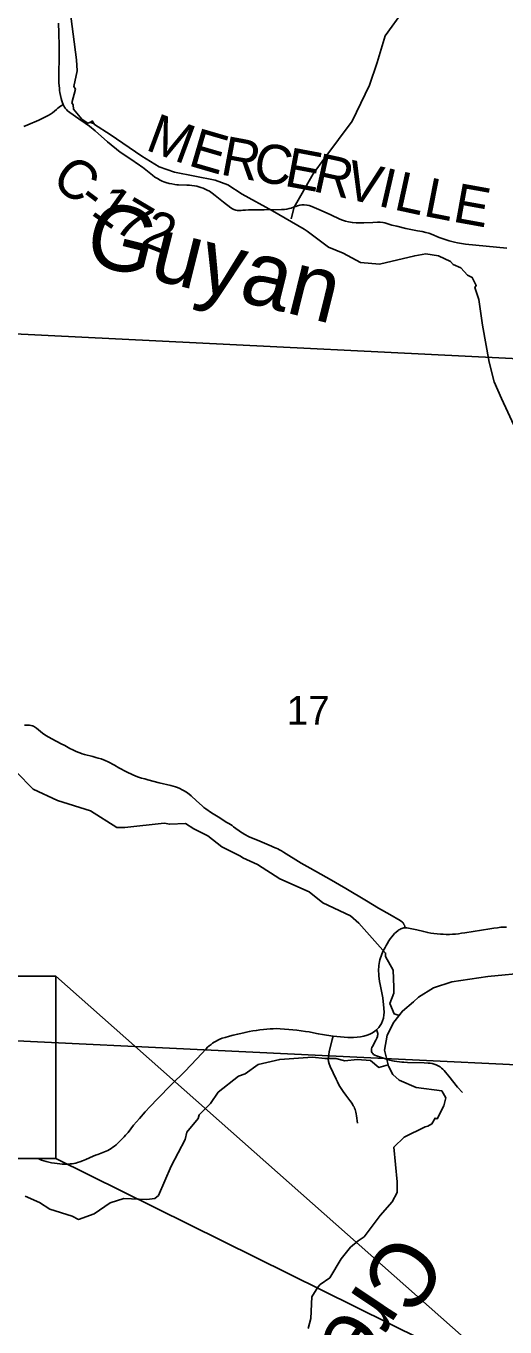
# Model space of a CAD drawing. Extents: x -2.1 to 31.9, y 6.3 to 28.3.
# Drawn here: x 2.564 to 3.259, y 23.525 to 25.414 of the extents above; entities that cross this region are included whole.
import ezdxf

# ---------------------------------------------------------------- set-up
doc = ezdxf.new("R2010")
doc.units = 0
for name, color, linetype in [('GM_X_County_Road', 7, 'Continuous'), ('GM_X_County_Road_Text', 7, 'Continuous'), ('GM_X_Minor_River', 7, 'Continuous'), ('GM_X_Minor_River_Text', 7, 'Continuous'), ('GM_X_Section', 7, 'Continuous'), ('GM_X_Section_Text', 7, 'Continuous'), ('GM_X_Township_Road', 7, 'Continuous'), ('TX_P_1', 7, 'Continuous')]:
    doc.layers.add(name, color=color, linetype=linetype)

msp = doc.modelspace()

# ---------------------------------------------------------------- linework, layer by layer
at = {"layer": 'GM_X_County_Road'}
for points in [[(2.611, 25.4185), (2.6113, 25.4136), (2.6115, 25.409), (2.6118, 25.403), (2.6119, 25.3974), (2.612, 25.3916), (2.612, 25.3708), (2.6117, 25.343), (2.6117, 25.3376), (2.6119, 25.3318), (2.6122, 25.3276), (2.6125, 25.3238), (2.6129, 25.3206), (2.6133, 25.3176), (2.6141, 25.3132), (2.615, 25.3091), (2.6159, 25.3056), (2.6168, 25.3027), (2.6179, 25.3001), (2.6188, 25.2983), (2.6198, 25.2966), (2.621, 25.2949), (2.6227, 25.293), (2.6245, 25.2912), (2.6276, 25.2887), (2.6405, 25.2795), (2.6454, 25.2763), (2.6498, 25.2733), (2.656, 25.2687), (2.6643, 25.2619), (2.6825, 25.2461), (2.7007, 25.2311), (2.7177, 25.2198), (2.7258, 25.2143), (2.7285, 25.2127), (2.7309, 25.211), (2.7331, 25.2093), (2.7477, 25.1975), (2.751, 25.195), (2.7547, 25.1927), (2.7587, 25.1906), (2.7614, 25.1892), (2.7641, 25.1881), (2.7668, 25.1872), (2.7717, 25.1858), (2.7759, 25.1849), (2.7798, 25.1843), (2.7828, 25.1839), (2.7855, 25.1837), (2.7973, 25.1834), (2.8013, 25.1832), (2.8048, 25.1828), (2.8084, 25.1822), (2.812, 25.1815), (2.815, 25.1807), (2.8178, 25.1798), (2.8212, 25.1786), (2.8242, 25.1774), (2.8271, 25.1761), (2.8301, 25.1743), (2.8342, 25.1717), (2.8385, 25.1682), (2.8505, 25.1586), (2.8612, 25.1501), (2.8636, 25.1487), (2.8658, 25.1477), (2.8683, 25.1468), (2.8708, 25.1463), (2.8736, 25.1462), (2.8762, 25.1464), (2.8789, 25.1467), (2.8826, 25.147), (2.8871, 25.1472), (2.9098, 25.1474), (2.9348, 25.1479), (2.9391, 25.1481), (2.9427, 25.1485), (2.9461, 25.1492), (2.949, 25.15), (2.9533, 25.1515), (2.9554, 25.1523), (2.9582, 25.1533), (2.9616, 25.1542), (2.9645, 25.1546), (2.9678, 25.1546), (2.9716, 25.1542), (2.975, 25.1535), (2.9789, 25.1521), (2.9922, 25.1463), (3.0062, 25.1399), (3.0192, 25.134), (3.0231, 25.1325), (3.0275, 25.131), (3.0321, 25.1299), (3.0377, 25.1289), (3.0432, 25.1284), (3.0483, 25.1283), (3.0542, 25.1284), (3.0675, 25.1289), (3.074, 25.1294), (3.0781, 25.1296), (3.0818, 25.1292), (3.0849, 25.1285), (3.0949, 25.1253), (3.102, 25.1236), (3.1153, 25.1204), (3.1323, 25.1171), (3.139, 25.1159), (3.1444, 25.1146), (3.1485, 25.1134), (3.1525, 25.1119), (3.1637, 25.1074), (3.1737, 25.1038), (3.1778, 25.1025), (3.182, 25.1013), (3.186, 25.1003), (3.19, 25.0996), (3.2016, 25.0977), (3.2318, 25.0944), (3.2618, 25.0916)], [(2.5618, 24.3989), (2.5645, 24.3992), (2.5667, 24.3992), (2.5692, 24.3991), (2.5713, 24.3987), (2.5734, 24.3982), (2.575, 24.3975), (2.5765, 24.3966), (2.5792, 24.3947), (2.5882, 24.3877), (2.593, 24.3843), (2.6018, 24.3795), (2.6153, 24.3722), (2.6202, 24.3695), (2.6278, 24.3654), (2.6319, 24.3634), (2.6361, 24.3615), (2.6391, 24.3601), (2.6421, 24.359), (2.6455, 24.3577), (2.6491, 24.3567), (2.6611, 24.3535), (2.6652, 24.3524), (2.669, 24.3514), (2.673, 24.3502), (2.6787, 24.3479), (2.6832, 24.3458), (2.6925, 24.3408), (2.6989, 24.3371), (2.7099, 24.3314), (2.7193, 24.327), (2.726, 24.3242), (2.7316, 24.3224), (2.7363, 24.321), (2.7408, 24.3197), (2.7575, 24.3156), (2.7744, 24.3114), (2.7776, 24.3105), (2.7809, 24.3096), (2.7841, 24.3085), (2.7872, 24.3071), (2.7908, 24.3054), (2.7937, 24.3037), (2.7961, 24.3022), (2.7984, 24.3007), (2.8036, 24.2964), (2.8114, 24.2893), (2.8197, 24.2819), (2.8223, 24.2797), (2.825, 24.2776), (2.8333, 24.2717), (2.8429, 24.2658), (2.8557, 24.258), (2.8583, 24.2564), (2.8607, 24.2549), (2.863, 24.2534), (2.8653, 24.2517), (2.8768, 24.2433), (2.8787, 24.2421), (2.8805, 24.241), (2.888, 24.2372), (2.9034, 24.2305), (2.9203, 24.2236), (2.9234, 24.2222), (2.9269, 24.2207), (2.9294, 24.2194), (2.932, 24.2181), (2.9346, 24.2165), (2.9378, 24.2145), (2.9634, 24.1988), (2.9765, 24.1914), (3.0074, 24.174), (3.0189, 24.1674), (3.028, 24.1618), (3.0579, 24.144), (3.0753, 24.1336), (3.0918, 24.1243), (3.107, 24.1153), (3.109, 24.114), (3.1102, 24.1131), (3.1109, 24.1124), (3.1114, 24.1117), (3.1121, 24.1106), (3.1125, 24.1096), (3.113, 24.1085), (3.114, 24.105)], [(2.5817, 23.7698), (2.5835, 23.769), (2.5868, 23.7676), (2.5901, 23.7665), (2.5934, 23.7655), (2.5973, 23.7646), (2.6013, 23.7637), (2.6052, 23.7631), (2.6091, 23.7625), (2.613, 23.7621), (2.6165, 23.7619), (2.6196, 23.7618), (2.6227, 23.7617), (2.6256, 23.7618), (2.6282, 23.762), (2.631, 23.7622), (2.6335, 23.7626), (2.6362, 23.7632), (2.639, 23.764), (2.6422, 23.765), (2.6459, 23.7666), (2.6507, 23.7687), (2.6615, 23.7733), (2.6647, 23.7746), (2.6681, 23.7758), (2.6755, 23.7785), (2.6781, 23.7795), (2.6804, 23.7806), (2.6827, 23.7817), (2.6852, 23.7831), (2.6876, 23.7846), (2.69, 23.7863), (2.6923, 23.7879), (2.6947, 23.7898), (2.6966, 23.7915), (2.6988, 23.7935), (2.7017, 23.7963), (2.7043, 23.799), (2.7065, 23.8013), (2.7086, 23.8038), (2.7121, 23.8078), (2.7202, 23.8181), (2.7245, 23.8233), (2.7286, 23.828), (2.7372, 23.8378), (2.7444, 23.8455), (2.755, 23.8566), (2.7753, 23.8772), (2.7943, 23.8962), (2.8121, 23.9148), (2.8254, 23.9292), (2.8276, 23.9314), (2.8299, 23.9335), (2.8326, 23.9356), (2.8347, 23.9373), (2.8371, 23.9389), (2.8398, 23.9404), (2.8426, 23.9418), (2.8455, 23.9431), (2.8487, 23.9444), (2.853, 23.9458), (2.8591, 23.9475), (2.8646, 23.949), (2.8713, 23.9506), (2.882, 23.9529), (2.8881, 23.9541), (2.8931, 23.9551), (2.8983, 23.956), (2.9033, 23.9567), (2.9088, 23.9573), (2.9133, 23.9577), (2.9184, 23.9581), (2.9226, 23.9583), (2.9271, 23.9585), (2.9327, 23.9583), (2.939, 23.9579), (2.9454, 23.9574), (2.9513, 23.9569), (2.9572, 23.9563), (2.9634, 23.9555), (2.9695, 23.9545), (2.975, 23.9536), (2.9814, 23.9523), (2.988, 23.9511), (2.9943, 23.9499), (3.0002, 23.9489), (3.0096, 23.9476), (3.0311, 23.9457), (3.035, 23.9455), (3.0391, 23.9455), (3.0444, 23.9459), (3.0496, 23.9466), (3.0543, 23.9475), (3.0589, 23.9489), (3.0629, 23.9504), (3.067, 23.9525), (3.0703, 23.9548), (3.0727, 23.9568), (3.076, 23.9602), (3.0778, 23.9628), (3.0798, 23.9661), (3.0813, 23.9696), (3.0826, 23.9739), (3.0834, 23.9783), (3.0836, 23.982), (3.0834, 23.9882), (3.0829, 23.9937), (3.0823, 23.9979), (3.0816, 24.003), (3.0778, 24.0228), (3.0771, 24.0269), (3.0764, 24.0314), (3.076, 24.0349), (3.0758, 24.0384), (3.0757, 24.0415), (3.0757, 24.0447), (3.0759, 24.0476), (3.0761, 24.0502), (3.0765, 24.0531), (3.0769, 24.0559), (3.0776, 24.0585), (3.0784, 24.0611), (3.0792, 24.0636), (3.0804, 24.0667), (3.0813, 24.069), (3.0823, 24.0714), (3.0837, 24.074), (3.085, 24.0765), (3.0864, 24.079), (3.0879, 24.0817), (3.0907, 24.0861), (3.0925, 24.0887), (3.0948, 24.0916), (3.097, 24.0943), (3.0989, 24.0965), (3.1012, 24.0986), (3.1039, 24.1009), (3.1052, 24.1018), (3.1066, 24.1025), (3.1078, 24.1032), (3.1094, 24.1038), (3.1109, 24.1043), (3.1122, 24.1047), (3.114, 24.105)], [(3.114, 24.105), (3.1154, 24.105), (3.1168, 24.1049), (3.119, 24.1046), (3.1213, 24.1041), (3.1313, 24.1017), (3.1411, 24.0993), (3.1469, 24.098), (3.1515, 24.0972), (3.156, 24.0966), (3.1604, 24.0961), (3.1653, 24.0957), (3.1695, 24.0955), (3.1737, 24.0953), (3.1784, 24.0953), (3.183, 24.0955), (3.1871, 24.0958), (3.1914, 24.0963), (3.1961, 24.0969), (3.2007, 24.0976), (3.2372, 24.1035), (3.243, 24.1044), (3.2482, 24.105), (3.253, 24.1056), (3.257, 24.1059), (3.2611, 24.106)]]:
    msp.add_lwpolyline(points, dxfattribs=at)
at = {"layer": 'GM_X_Minor_River'}
for points in [[(2.9487, 25.1342), (2.9532, 25.1511), (2.9808, 25.1996), (2.9978, 25.223), (3.0375, 25.276), (3.0626, 25.3284), (3.0734, 25.3615), (3.0851, 25.3998), (3.112, 25.4366), (3.1422, 25.4975), (3.2102, 25.5853), (3.2265, 25.5996)], [(3.2753, 24.8276), (3.2541, 24.8732), (3.2431, 24.8975), (3.2363, 24.9263), (3.2264, 24.9799), (3.2211, 25.0171), (3.2154, 25.0346), (3.2173, 25.0376), (3.2116, 25.049), (3.2044, 25.0524), (3.195, 25.0631), (3.1836, 25.068), (3.1798, 25.0725), (3.1624, 25.0805), (3.1443, 25.0835), (3.128, 25.0808), (3.077, 25.0685), (3.0494, 25.0711), (3.0241, 25.0843), (3.0029, 25.093), (2.9719, 25.1165), (2.9677, 25.1192), (2.9216, 25.146), (2.8777, 25.1699), (2.8569, 25.1839), (2.8384, 25.1903), (2.7794, 25.2019), (2.7571, 25.2099), (2.7321, 25.2254), (2.686, 25.2568), (2.6636, 25.2712), (2.6602, 25.2765), (2.658, 25.2742), (2.6606, 25.2731), (2.6583, 25.2735), (2.6599, 25.2754), (2.6538, 25.2731), (2.6451, 25.2788), (2.633, 25.2936), (2.6326, 25.3), (2.6307, 25.3027), (2.636, 25.3228), (2.6337, 25.3266), (2.6382, 25.3494), (2.6375, 25.365), (2.626, 25.4509)], [(3.1053, 23.9777), (3.098, 23.9801), (3.092, 23.9949), (3.0976, 24.0101), (3.0976, 24.0188), (3.0969, 24.0432), (3.0859, 24.0633), (3.0859, 24.0682), (3.0469, 24.1118), (3.0348, 24.1224), (2.9947, 24.141), (2.975, 24.1569), (2.9323, 24.1762), (2.8998, 24.197), (2.8786, 24.2064), (2.8752, 24.2087), (2.8483, 24.2223), (2.8279, 24.2386), (2.8075, 24.2488), (2.7954, 24.2564), (2.7727, 24.2552), (2.7644, 24.2567), (2.7077, 24.2505), (2.696, 24.2505), (2.6578, 24.2747), (2.6097, 24.2898), (2.5746, 24.306), (2.55, 24.3314)], [(3.0215, 23.624), (3.0349, 23.6413), (3.0458, 23.6504), (3.0549, 23.6562), (3.0779, 23.687), (3.0953, 23.7068), (3.1024, 23.7205), (3.1024, 23.7361), (3.0978, 23.7862), (3.1126, 23.8007), (3.1432, 23.816), (3.1473, 23.8171), (3.153, 23.8202), (3.1575, 23.8286), (3.1606, 23.8274), (3.1704, 23.8465), (3.173, 23.8579), (3.1673, 23.8681), (3.1303, 23.873), (3.1057, 23.8839), (3.0962, 23.8919), (3.0898, 23.904), (3.0841, 23.9272), (3.0882, 23.9489), (3.0977, 23.9679), (3.1101, 23.9839), (3.1264, 23.9976), (3.1336, 24.0041), (3.1551, 24.0178), (3.1819, 24.0263), (3.2341, 24.034), (3.2946, 24.0402)], [(3.0894, 23.9057), (3.0758, 23.9021), (3.0637, 23.9123), (3.0444, 23.9138), (3.0267, 23.9115), (3.0134, 23.9153), (2.9976, 23.9152), (2.9798, 23.9171), (2.9322, 23.9139), (2.9008, 23.9066), (2.8823, 23.8929), (2.8725, 23.8895), (2.843, 23.8662), (2.832, 23.8498), (2.8154, 23.8335), (2.8139, 23.8281), (2.7973, 23.808), (2.795, 23.7977), (2.7747, 23.7589), (2.7562, 23.7163), (2.7509, 23.7117), (2.7396, 23.7105), (2.7059, 23.7116), (2.6863, 23.7055), (2.6628, 23.6894), (2.6402, 23.6814), (2.6311, 23.6863), (2.5986, 23.6965), (2.5838, 23.706), (2.563, 23.7154)], [(2.9737, 23.5233), (2.9771, 23.5378), (2.979, 23.569), (2.9873, 23.583), (2.991, 23.5872), (3.005, 23.5968), (3.0215, 23.624)]]:
    msp.add_lwpolyline(points, dxfattribs=at)
at = {"layer": 'GM_X_Section'}
for points in [[(2.5466, 25.9887), (3.6038, 25.9379), (3.5328, 24.9185), (2.4786, 24.9709)], [(2.4786, 24.9709), (3.5328, 24.9185), (3.4671, 23.8965), (2.4194, 23.947)], [(2.4194, 23.947), (3.4671, 23.8965), (3.4412, 23.4777), (3.416, 23.0562), (3.4084, 22.8979), (2.8085, 22.9264), (2.3612, 22.9526), (2.3614, 22.9562), (2.3709, 23.1348), (2.3938, 23.5483)]]:
    msp.add_lwpolyline(points, close=True, dxfattribs=at)
at = {"layer": 'GM_X_Township_Road'}
for points in [[(2.5608, 25.2685), (2.5666, 25.2708), (2.5826, 25.2778), (2.5904, 25.2815), (2.596, 25.2843), (2.5995, 25.2864), (2.6023, 25.2883), (2.6055, 25.2908), (2.6081, 25.2929), (2.6105, 25.295), (2.6123, 25.2965), (2.6141, 25.2978), (2.616, 25.299), (2.6179, 25.3001)], [(3.0727, 23.9568), (3.0736, 23.9542), (3.074, 23.9529), (3.0743, 23.9513), (3.0744, 23.9497), (3.0742, 23.9483), (3.0739, 23.9469), (3.0731, 23.9445), (3.0718, 23.9419), (3.0668, 23.9326), (3.066, 23.931), (3.0654, 23.9293), (3.0653, 23.9275), (3.0653, 23.9263), (3.0655, 23.925), (3.0661, 23.9234), (3.0671, 23.9222), (3.0684, 23.9211), (3.0702, 23.9201), (3.0726, 23.9191), (3.0886, 23.9138), (3.0921, 23.9128), (3.0958, 23.9118), (3.0987, 23.9112), (3.1019, 23.9107), (3.1058, 23.9101), (3.1092, 23.9098), (3.1123, 23.9096), (3.1174, 23.9093), (3.1417, 23.9087), (3.1476, 23.9085), (3.1507, 23.9083), (3.1535, 23.9077), (3.1564, 23.9069), (3.1593, 23.9058), (3.1622, 23.9045), (3.1648, 23.9029), (3.1671, 23.9013), (3.169, 23.8998), (3.171, 23.8976), (3.1728, 23.8955), (3.1777, 23.8895), (3.1902, 23.8736), (3.1972, 23.8656)], [(3.0448, 23.821), (3.0435, 23.8319), (3.0432, 23.8346), (3.0428, 23.8372), (3.0423, 23.839), (3.0416, 23.8411), (3.0409, 23.8429), (3.04, 23.8447), (3.0389, 23.8466), (3.0376, 23.8488), (3.0359, 23.8515), (3.034, 23.8541), (3.028, 23.8621), (3.0244, 23.8671), (3.0213, 23.8717), (3.0186, 23.8761), (3.0158, 23.881), (3.0139, 23.8849), (3.0054, 23.9033), (3.0039, 23.9073), (3.003, 23.911), (3.0027, 23.9141), (3.0028, 23.9172), (3.0033, 23.9211), (3.0041, 23.9249), (3.0083, 23.9425), (3.0096, 23.9476)]]:
    msp.add_lwpolyline(points, dxfattribs=at)
at = {"layer": 'TX_P_1'}
for points in [[(1.2977, 23.7698), (2.6072, 23.7698), (2.6072, 24.0345), (1.2977, 24.0345)], [(2.6072, 24.0345), (3.2845, 23.4344), (2.6072, 23.7698)]]:
    msp.add_lwpolyline(points, close=True, dxfattribs=at)

# ---------------------------------------------------------------- texts
at = {"layer": 'GM_X_County_Road_Text'}
for s, rotation, p in [('M', 339.67, (2.7357, 25.2351)), ('E', 343.7296, (2.7977, 25.2123)), ('R', 349.4099, (2.8445, 25.199)), ('C', 350.5171, (2.8916, 25.1902)), ('E', 349.3137, (2.9373, 25.1826)), ('C', 321.9763, (2.5985, 25.1866)), ('R', 347.667, (2.9786, 25.1748)), ('V', 347.0302, (3.0241, 25.1648)), ('I', 347.0574, (3.0728, 25.1536)), ('L', 347.6943, (3.0962, 25.1482)), ('L', 348.934, (3.1391, 25.1389)), ('E', 349.7491, (3.1816, 25.1306)), ('-', 322.995, (2.6362, 25.1572)), ('1', 324.6859, (2.6563, 25.142)), ('7', 329.3821, (2.6891, 25.119)), ('2', 338.7231, (2.7283, 25.0968))]:
    msp.add_text(s, height=0.0568, rotation=rotation, dxfattribs=at).set_placement(p)
at = {"layer": 'GM_X_Minor_River_Text'}
for s, rotation, p in [('Guyan', 346.0032, (2.645, 25.0719)), ('Creek', 236.1304, (3.0983, 23.6674))]:
    msp.add_text(s, height=0.09469, rotation=rotation, dxfattribs=at).set_placement(p)
at = {"layer": 'GM_X_Section_Text'}
msp.add_text('17', height=0.04186, rotation=0, dxfattribs=at).set_placement((2.9424, 24.3998))

doc.saveas('drawing.dxf')
